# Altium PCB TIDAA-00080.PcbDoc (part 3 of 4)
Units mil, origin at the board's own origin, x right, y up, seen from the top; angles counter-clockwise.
Board outline 7874.02 x 2559.06 mil, 4 copper layers (Top Layer, MidLayer1, MidLayer2, Bottom Layer), stack 61.2 mil thick; 363 components, 169 nets, 940 pads, 199 vias.
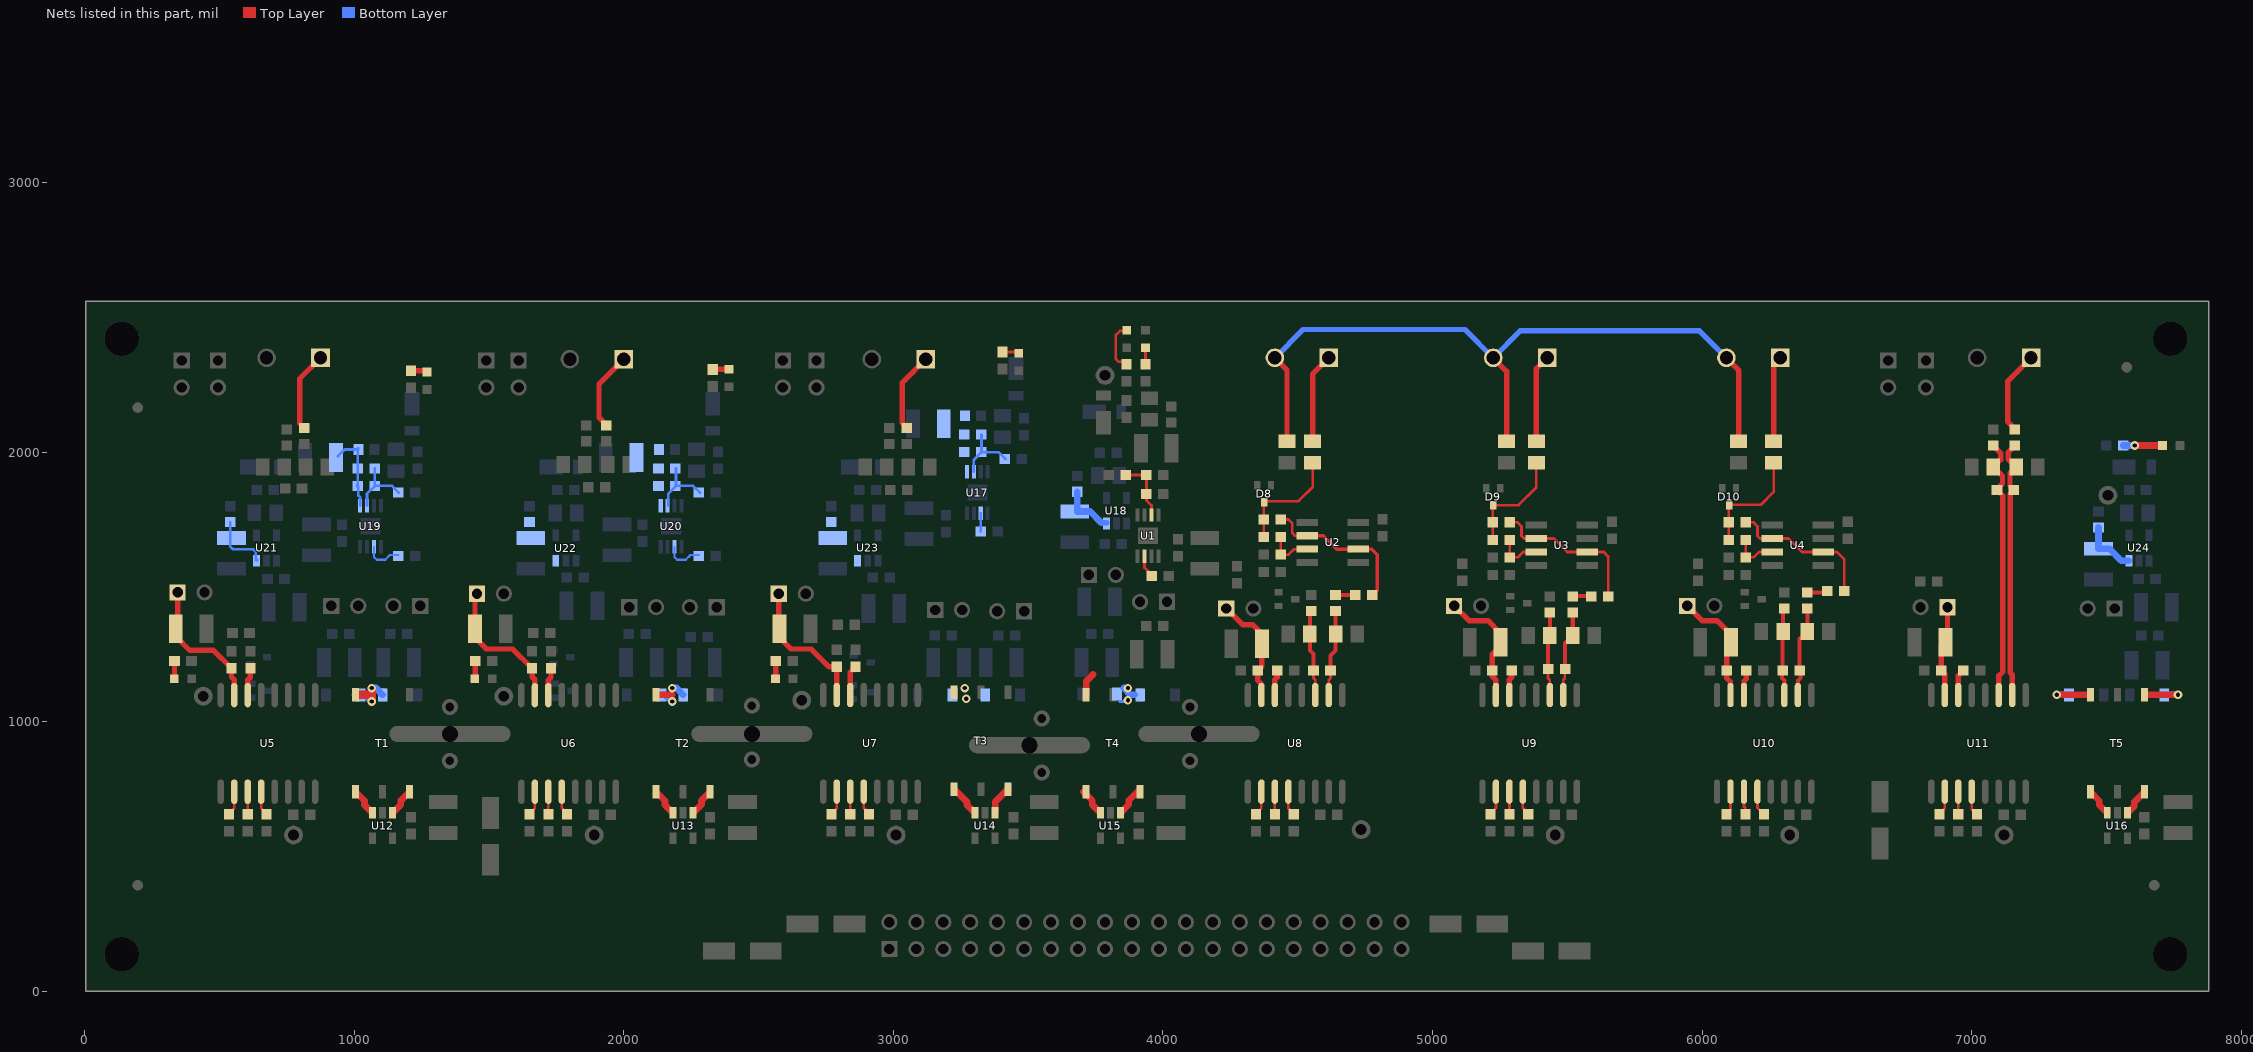
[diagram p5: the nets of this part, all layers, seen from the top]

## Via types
v1: diameter 32, hole 16, Top Layer to Bottom Layer, tented both sides, 199 vias

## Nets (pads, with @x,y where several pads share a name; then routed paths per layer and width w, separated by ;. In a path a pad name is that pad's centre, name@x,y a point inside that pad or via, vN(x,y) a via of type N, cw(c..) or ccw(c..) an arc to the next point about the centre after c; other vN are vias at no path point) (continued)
NetC10_2: C10.2 C16.2 FB16.2 U11.3 | length 986.6
  Top Layer w20: FB16.2@7080,2025.47 7080,2023.5 7107.2,1996.3 7107.2,1972.2 C10.2@7080,1945 7114,1911 7114,1884 7093.5,1863.5 C16.2@7093.5,1860 7115,1838.5 7115,1185 7100,1170 U11.3@7100,1099.13
NetC11_1: C11.1 C16.1 FB6.2 U11.2 | length 971
  Top Layer w20: U11.2@7150,1099.13 7150,1175 7143,1182 7143,1846.5 C16.1@7156.5,1860 7142,1874.5 7142,1922 C11.1@7165,1945 7135.2,1974.8 7135.2,1998.7 FB6.2@7160,2023.5
NetC15_1: C15.1 R14.2 R15.1 U1.2 | length 235
  Top Layer w10: R14.2@3860,1915 R14.2@3861.5,1915 R15.1@3938.5,1915 3938.5,1846.5 C15.1@3940,1845 ; C15.1@3938.5,1845 3938.5,1821.5 3957.4,1802.6 U1.2@3957.4,1767
NetC17_2: C17.2 C46.1 J26.1 U5.7 | length 525.9
  Top Layer w20: C17.2@332.91,1345 345,1357.09 J26.1@345,1480 ; C17.2@342.91,1345 342.91,1312.09 390,1265 477.65,1265 544.15,1198.5 C46.1@545,1198.5 545,1166 555,1156 U5.7@555,1098.82
NetC18_2: C18.2 C47.1 J27.1 U6.7 | length 528.8
  Top Layer w20: J27.1@1455,1475 1447.91,1467.91 C18.2@1447.91,1345 1447.91,1312.09 1490,1270 1587.65,1270 1659.15,1198.5 C47.1@1660,1198.5 1660,1166 1670,1156 U6.7@1670,1098.82
NetC19_2: C19.2 C56.1 J31.1 U11.7 | length 341.2
  Top Layer w20: U11.7@6900,1099.13 6900,1176.5 C56.1@6886.5,1190 6886.5,1279.41 C19.2@6902.09,1295 6910,1302.91 J31.1@6910,1425
NetC21_1: C21.1 R16.2 U2.3 | length 171.8
  Top Layer w10: R16.2@4436.5,1685 C21.1@4436.5,1620 4466.02,1620 4486.02,1640 U2.3@4535,1640
NetC23_1: C23.1 R17.2 U3.3 | length 171.8
  Top Layer w10: R17.2@5286.5,1675 C23.1@5286.5,1610 5316.02,1610 5336.02,1630 U3.3@5385,1630
NetC25_1: C25.1 R18.2 U4.3 | length 171.8
  Top Layer w10: R18.2@6161.5,1675 C25.1@6161.5,1610 6191.02,1610 6211.02,1630 U4.3@6260,1630
NetC27_2: C27.2 U1.6 | length 85.7
  Top Layer w10: U1.6@3931.8,1613.4 3931.8,1571 3932.84,1571 3951,1552.84 3951,1549 C27.2@3960,1540
NetC37_2: C37.2 C51.2 FB19.2 U8.3 | length 315.8
  Top Layer w10: C51.2@4558.5,1190 4558.5,1161.5 4565,1155 U8.3@4565,1105
  Top Layer w15: FB19.2@4550,1410.47 4545,1405.47 C37.2@4545,1325 4545,1265 4558.5,1251.5 C51.2@4558.5,1190
NetC38_2: C38.2 C51.1 FB18.2 U8.2 | length 320.4
  Top Layer w10: U8.2@4615,1100 4615,1155 4621.5,1161.5 C51.1@4621.5,1190 ; C51.1@4619.1,1189.1 C51.1@4620.6,1189.1
  Top Layer w15: C51.1@4621.5,1190 4621.5,1246.5 4640,1265 C38.2@4640,1325 FB18.2@4640,1408.5
NetC40_2: C40.2 C53.2 FB21.2 U9.3 | length 299.6
  Top Layer w10: C53.2@5428.5,1190 5428.5,1161.5 5435,1155 U9.3@5435,1105
  Top Layer w15: C53.2@5428.5,1195 5428.5,1313.5 C40.2@5435,1320 FB21.2@5435,1403.5 ; FB21.2@5435.98,1404.49 FB21.2@5436.5,1405
NetC41_2: C41.2 C53.1 FB20.2 U9.2 | length 326
  Top Layer w10: U9.2@5485,1090 U9.2@5485,1099.13 5485,1155 5490,1160 5490,1190 C53.1@5491.5,1190
  Top Layer w15: C53.1@5491.5,1195 5491.5,1291.5 C41.2@5520,1320 5520,1403.5 FB20.2@5518.5,1405
NetC43_2: C43.2 C55.2 FB23.2 U10.3 | length 328.8
  Top Layer w15: U10.3@6305,1099.13 6305,1153.73 6296,1162.73 6296,1187.5 C55.2@6298.5,1190 6298.5,1333.5 C43.2@6300,1335 6300,1415.47 FB23.2@6305,1420.47
NetC44_2: C44.2 C55.1 FB22.2 U10.2 | length 335.9
  Top Layer w15: U10.2@6355,1099.13 6355,1153.73 6364,1162.73 6364,1187.5 C55.1@6361.5,1190 6361.5,1306.5 C44.2@6390,1335 FB22.2@6390,1418.5
NetC48_1: C48.1 C146.2 J22.1 U7.7 | length 525.6
  Top Layer w20: J22.1@2575,1475 2575,1347.91 C146.2@2577.91,1345 2577.91,1312.09 2620,1270 2695,1270 2761.5,1203.5 C48.1@2790,1203.5 U7.7@2790,1099.13
NetC50_1: C50.1 C147.2 J28.1 U8.7 | length 409.3
  Top Layer w10: U8.7@4365,1099.13 U8.7@4365,1105
  Top Layer w20: J28.1@4235,1420 4295,1360 4332,1360 4367.09,1324.91 C147.2@4367.09,1290 4367.09,1205.59 C50.1@4351.5,1190 4351.5,1153.5 4365,1140 U8.7@4365,1105
NetC52_1: C52.1 C148.2 J29.1 U9.7 | length 454.7
  Top Layer w10: C52.1@5220,1190 C52.1@5221.5,1188.5 ; C52.1@5221.5,1175 C52.1@5221.5,1188.5 ; C52.1@5221.5,1190 C52.1@5221.5,1188.5
  Top Layer w20: J29.1@5080,1430 5135,1375 5205,1375 5252.09,1327.91 C148.2@5252.09,1295 ; C52.1@5221.5,1175 5221.5,1168.5 5235,1155 U9.7@5235,1099.13 ; C52.1@5221.5,1190 5221.5,1251.5 C148.2@5255,1285
NetC54_1: C54.1 C149.2 J30.1 U10.7 | length 421.4
  Top Layer w20: J30.1@5945,1430 6000,1375 6055,1375 6107.09,1322.91 C149.2@6107.09,1295 6091.5,1279.41 C54.1@6091.5,1190 6091.5,1161.5 6105,1147.99 U10.7@6105,1120
NetC84_2: C84.2 C94.2 FB8.1 R59.2 U17.1
NetC88_2: C88.2 C97.2 FB9.1 R61.2 U19.1 | length 302.9
  Bottom Layer w10: C88.2@940,1985 965,2010 FB9.1@1013.5,2010 ; C97.2@1010,1875 1015,1870 1015,1840 1022,1833 U19.1@1022,1802 ; C97.2@1013.5,1876.5 R61.2@1013.5,1940 FB9.1@1013.5,2010 ; FB9.1@1015,2015 1013.5,2013.5 FB9.1@1013.5,2010 ; FB9.1@1015.47,2010 FB9.1@1013.5,2010
NetC91_2: C91.2 C99.2 FB10.1 R62.2 U20.1
NetC94_1: C94.1 R59.1 R63.2 U17.2 | length 242.3
  Bottom Layer w10: U17.2@3298.11,1927 3298.11,1971.1 3327.01,2000 3390.51,2000 R63.2@3415.51,1975 ; C94.1@3327.01,2006.5 R59.1@3327.01,2065
NetC97_1: C97.1 R61.1 R64.2 U19.2 | length 242.3
  Bottom Layer w10: U19.2@1047.6,1802 1047.6,1846.1 C97.1@1076.5,1875 1140,1875 R64.2@1165,1850 ; C97.1@1076.5,1881.5 R61.1@1076.5,1940
NetC99_1: C99.1 R62.1 R65.2 U20.2 | length 242.3
  Bottom Layer w10: U20.2@2165,1802 2165,1846.1 2193.9,1875 2257.4,1875 R65.2@2282.4,1850 ; C99.1@2193.9,1881.5 R62.1@2193.9,1940
NetC110_2: C110.2 U17.6 | length 68.6
  Bottom Layer w8: C110.2@3323.5,1705 3324,1705.5 U17.6@3324,1773.4
NetC111_2: C111.2 FB11.1 U18.3 | length 200.8
  Bottom Layer w20: 3772.4,1737.76 U18.3@3792.4,1737.76
  Bottom Layer w25: FB11.1@3682.4,1853.23 3682.4,1779.84 3730.31,1779.84 3772.4,1737.76
NetC113_2: C113.2 FB12.1 U21.3 | length 228.8
  Bottom Layer w10: FB12.1@540,1740.47 540,1682.09 540,1650 550,1640 625,1640 635,1630 635,1600 U21.3@640,1600
NetC116_2: C116.2 U19.6 | length 139.1
  Bottom Layer w8: U19.6@1073.2,1648.4 1073.2,1610.8 1083,1601 1115,1601 1132.3,1618.3 C116.2@1163.5,1618.3
NetC117_2: C117.2 FB13.1 U22.3
NetC120_2: C120.2 U20.6 | length 139.1
  Bottom Layer w8: U20.6@2188.2,1648.4 2188.2,1610.8 2198,1601 2230,1601 2247.3,1618.3 C120.2@2278.5,1618.3
NetC121_2: C121.2 FB14.1 U23.3
NetC123_2: C123.2 FB15.1 U24.3 | length 209.3
  Bottom Layer w25: FB15.1@7470,1720.47 C123.2@7470,1642.09 7510,1642.09 7554.33,1597.76 U24.3@7582.6,1597.76
NetD1_1: D1.1 R1.1 | length 180.4
  Top Layer w10: R1.1@3865,2335 3835,2335 3825,2345 3825,2435 3840,2450 D1.1@3865,2450
NetD2_2: D2.2 R2.1 | length 68.5
  Top Layer w10: R2.1@3935,2326.5 D2.2@3935,2387.52 D2.2@3935,2395
NetD3_1: D3.1 R5.1 | length 61.7
  Top Layer w10: R5.1@3405,2371.5 3460.98,2371.5 D3.1@3465,2367.48
NetD4_1: D4.1 R3.1 | length 61.7
  Top Layer w20: R3.1@1210,2301.5 1265.98,2301.5 D4.1@1270,2297.48
NetD5_1: D5.1 R4.1 | length 60.4
  Top Layer w20: R4.1@2330,2306.5 2330.98,2307.48 D5.1@2390,2307.48
NetD7_2: D7.2 R60.1 | length 146
  Top Layer w25: v1(7605,2025) D7.2@7707.52,2025
  Bottom Layer w25: R60.1@7561.5,2025 v1(7605,2025)
NetD8_3: D8.3 R6.1 R7.2 R16.1 | length 432.1
  Top Layer w10: R6.1@4372.01,1755 4373.5,1753.5 R16.1@4373.5,1680 ; R6.1@4373.5,1755 4373.5,1817.01 4375,1818.5 4503.5,1818.5 4555,1870 R7.2@4555,1960 ; R6.1@4374.25,1754.25 R6.1@4375,1755
NetD9_3: D9.3 R9.1 R10.2 R17.1 | length 418.3
  Top Layer w10: R9.1@5222.01,1740 5223.5,1738.5 R17.1@5223.5,1675 R17.1@5223.5,1665 ; R9.1@5223.5,1740 5223.5,1802.01 D9.3@5225,1803.5 5318.5,1803.5 5385,1870 R10.2@5385,1960 ; R9.1@5224.25,1739.25 R9.1@5225,1740
NetD10_3: D10.3 R12.1 R13.2 R18.1 | length 425.1
  Top Layer w10: R12.1@6097.01,1741.5 R12.1@6098.5,1740 R18.1@6098.5,1675 ; R12.1@6098.5,1741.5 6098.5,1803.5 6100,1805 6218.5,1805 6265,1851.5 R13.2@6265,1960 ; R12.1@6099.25,1740.75 R12.1@6100,1741.5
NetD14_2: D14.2 R28.1 | length 65.4
  Top Layer w20: D14.2@332.52,1160 333.5,1160.98 R28.1@333.5,1225
NetD15_2: D15.2 R30.1 | length 65.4
  Top Layer w20: D15.2@1447.52,1160 1448.5,1160.98 R30.1@1448.5,1225
NetD16_2: D16.2 R32.1 | length 65.4
  Top Layer w20: D16.2@2562.52,1160 2563.5,1160.98 R32.1@2563.5,1225
NetD29_2: D29.2 D30.1 T1.6 | length 211.3
  Top Layer w25: T1.6@1005,1099.84 T1.6@1005.16,1100
  Top Layer w32: T1.6@1005.16,1100 1065,1100 ; v1(1065,1075) 1065,1100 ; v1(1065,1125) 1065,1100
  Bottom Layer w25: D29.2@1025,1100 1040,1100 v1(1065,1075) ; v1(1065,1125) 1080.53,1125 D30.1@1105.53,1100
NetD32_2: D32.2 D33.1 T2.6 | length 161.3
  Top Layer w25: T2.6@2120,1099.84 2179.84,1099.84 2180,1100
  Bottom Layer w25: D32.2@2140,1100 2155,1100 v1(2180,1075) ; v1(2180,1125) 2195.53,1125 D33.1@2220.53,1100
NetD35_2: D35.2 D36.1 T3.6
  other v1: 3270,1085 3265,1125
NetD37_2: D37.2 D38.1 T4.6 | length 169
  Top Layer w25: T4.6@3715,1099.84 3715,1150 3740,1175
  Bottom Layer w12: 3839.47,1075 3865,1075 v1(3870,1080)
  Bottom Layer w25: v1@3855,1125 3880,1100 3895.53,1100
  other v1: 3870,1125
NetD39_2: D39.2 T5.6 | length 170.6
  Top Layer w25: v1(7315.16,1099.84) T5.6@7440,1099.84
  Bottom Layer w25: v1(7315.16,1099.84) 7315,1100 D39.2@7360.53,1100
NetD40_2: D40.2 T5.4 | length 175.3
  Top Layer w25: T5.4@7640,1099.84 v1(7764.84,1099.84)
  Bottom Layer w25: D40.2@7714.47,1100 7764.68,1100 v1(7764.84,1099.84)
NetFB2_1: FB2.1 J9.1 | length 299.4
  Top Layer w20: FB2.1@815,2089.53 798,2106.53 798,2273 J9.1@875,2350
NetFB4_1: FB4.1 J10.1 | length 294.8
  Top Layer w20: FB4.1@1935,2099.53 1935,2101.5 1908,2128.5 1908,2253 J10.1@2000,2345
NetFB6_1: FB6.1 J15.1 | length 310.7
  Top Layer w20: FB6.1@7160,2086.5 7133,2113.5 7133,2263 J15.1@7220,2350
NetFB7_1: FB7.1 J11.1 | length 296.6
  Top Layer w20: FB7.1@3050,2091.5 3033,2108.5 3033,2258 J11.1@3120,2345
NetFB18_1: FB18.1 R21.2 | length 73.7
  Top Layer w15: FB18.1@4640,1469.53 4640.47,1470 R21.2@4713.5,1470
NetFB20_1: FB20.1 R24.2 | length 69.1
  Top Layer w15: FB20.1@5520,1466.5 5587.01,1466.5 R24.2@5588.5,1465
NetFB22_1: FB22.1 R27.2 | length 70.8
  Top Layer w15: FB22.1@6390,1479.53 6458.03,1479.53 R27.2@6460,1481.5
NetJ12_1: J12.1 R7.1 | length 334.9
  Top Layer w20: R7.1@4555,2040 4555,2290 J12.1@4615,2350
NetJ13_1: J13.1 R10.1 | length 326.6
  Top Layer w20: R10.1@5385,2040 5385,2310 J13.1@5425,2350
NetJ14_1: J14.1 R13.1 | length 320.4
  Top Layer w20: R13.1@6265,2040 6265,2325 J14.1@6290,2350
NetR6_2: R6.2 R21.1 U2.2 U2.6 | length 587
  Top Layer w10: R6.2@4440,1750 4465,1750 4480,1735 4480,1700 4490,1690 U2.2@4535,1690
  Top Layer w12: U2.2@4535,1690 4595,1690 4645,1640 U2.6@4724,1640 4775,1640 4795,1620 4795,1488.5 R21.1@4776.5,1470
NetR9_2: R9.2 R24.1 U3.2 U3.6 | length 586.4
  Top Layer w10: R9.2@5286.5,1740 5315,1740 5330,1725 5330,1690 5340,1680 U3.2@5385,1680 5450,1680 5500,1630 U3.6@5574,1630 5635,1630 5651.5,1613.5 R24.1@5651.5,1465
NetR12_2: R12.2 R27.1 U4.2 U4.6 | length 555.5
  Top Layer w10: R12.2@6161.5,1740 6190,1740 6205,1725 6205,1690 6215,1680 U4.2@6260,1680 6320,1680 6370,1630 U4.6@6445,1630 ; U4.6@6450,1630 6500,1630 6526.5,1603.5 R27.1@6526.5,1485
NetR29_2: R29.2 U5.6 | length 103.8
  Top Layer w20: U5.6@605,1098.82 605,1155 615,1165 R29.2@615,1198.5
NetR31_2: R31.2 U6.6 | length 103.8
  Top Layer w20: U6.6@1720,1098.82 1720,1155 1730,1165 R31.2@1730,1198.5
NetR33_2: R33.2 U7.6 | length 112.7
  Top Layer w20: U7.6@2840,1099.13 2840,1183.5 R33.2@2860,1203.5
NetR34_2: R34.2 U8.6 | length 94.4
  Top Layer w20: U8.6@4415,1099.13 4415,1156.73 4423.5,1165.24 R34.2@4423.5,1190
NetR35_2: R35.2 U9.6 | length 94.4
  Top Layer w20: U9.6@5285,1099.13 5285,1156.73 5293.5,1165.24 R35.2@5293.5,1190
NetR36_2: R36.2 U10.6 | length 94.4
  Top Layer w20: U10.6@6155,1099.13 6155,1150 6163.5,1158.5 R36.2@6163.5,1190
NetR37_2: R37.2 U11.6 | length 98.5
  Top Layer w20: U11.6@6950,1099.13 6950,1155 6950,1171.5 R37.2@6968.5,1190
NetR38_1: R38.1 U5.10 | length 95.9
  Top Layer w10: R38.1@530,655 555,680 U5.10@555,740.55
NetR39_1: R39.1 U5.11 | length 87.6
  Top Layer w10: U5.11@605,740.55 605,660 R39.1@610,655
NetR40_1: R40.1 U5.12 | length 88.8
  Top Layer w10: U5.12@655,740.55 655,680 R40.1@675,660
NetR41_1: R41.1 U6.10 | length 98.8
  Top Layer w10: R41.1@1650,650 1650,660 1670,680 U6.10@1670,740.55
NetR42_1: R42.1 U6.11 | length 95.6
  Top Layer w10: R42.1@1720,645 U6.11@1720,740.55
NetR43_1: R43.1 U6.12 | length 93.8
  Top Layer w10: U6.12@1770,740.55 1770,680 1790,660 R43.1@1790,656.5 R43.1@1790,655
NetR44_1: R44.1 U7.10 | length 89.2
  Top Layer w10: R44.1@2770,660 2790,680 U7.10@2790,740.87
NetR45_1: R45.1 U7.12 | length 94.2
  Top Layer w10: U7.12@2890,740.87 2890,680 2910,660 R45.1@2910,656.5 R45.1@2910,655
NetR46_1: R46.1 U7.11 | length 85.9
  Top Layer w10: R46.1@2840,655 R46.1@2840,656.5 U7.11@2840,740.87
NetR47_1: R47.1 U8.10 | length 94.2
  Top Layer w10: R47.1@4345,655 R47.1@4345,656.5 4345,660 4365,680 U8.10@4365,740.87
NetR48_1: R48.1 U8.11 | length 85.9
  Top Layer w10: R48.1@4415,655 R48.1@4415,656.5 U8.11@4415,740.87
NetR49_1: R49.1 U8.12 | length 94.2
  Top Layer w10: U8.12@4465,740.87 4465,680 4485,660 R49.1@4485,656.5 R49.1@4485,655
NetR50_1: R50.1 U9.10 | length 94.2
  Top Layer w10: R50.1@5215,655 R50.1@5215,656.5 5215,660 5235,680 U9.10@5235,740.87
NetR51_1: R51.1 U9.11 | length 85.9
  Top Layer w10: R51.1@5285,655 R51.1@5285,656.5 U9.11@5285,740.87
NetR52_1: R52.1 U9.12 | length 94.2
  Top Layer w10: U9.12@5335,740.87 5335,680 5355,660 R52.1@5355,656.5 R52.1@5355,655
NetR53_1: R53.1 U10.10 | length 92.1
  Top Layer w10: R53.1@6090,655 R53.1@6090,656.5 6090,660 6105,675 U10.10@6105,740.87
NetR54_1: R54.1 U10.12 | length 96.2
  Top Layer w10: U10.12@6205,740.87 6205,680 R54.1@6230,655
NetR55_1: R55.1 U10.11 | length 82.9
  Top Layer w10: U10.11@6155,740.87 6155,685 6160,680 R55.1@6160,660
NetR56_1: R56.1 U11.10 | length 94.2
  Top Layer w10: R56.1@6880,655 R56.1@6880,656.5 6880,660 6900,680 U11.10@6900,740.87
NetR57_1: R57.1 U11.12 | length 94.2
  Top Layer w10: U11.12@7000,740.87 7000,675 R57.1@7020,655
NetR58_1: R58.1 U11.11 | length 85.9
  Top Layer w10: R58.1@6950,655 R58.1@6950,656.5 U11.11@6950,740.87
NetT1_1: T1.1 U12.3 | length 103.7
  Top Layer w25: T1.1@1005,740 1038,707 1038,691.84 U12.3@1067.6,662.24
NetT1_3: T1.3 U12.1 | length 103.7
  Top Layer w25: U12.1@1142.4,662.24 1173,692.84 1173,708 T1.3@1205,740
NetT2_1: T2.1 U13.3 | length 103.7
  Top Layer w25: T2.1@2120,740 2153,707 2153,691.84 U13.3@2182.6,662.24
NetT2_3: T2.3 U13.1 | length 103.7
  Top Layer w25: U13.1@2257.4,662.24 2288,692.84 2288,708 T2.3@2320,740
NetT3_1: T3.1 U14.3 | length 119.9
  Top Layer w25: T3.1@3225,750 3273,702 3273,691.84 U14.3@3302.6,662.24
NetT3_3: T3.3 U14.1 | length 107.5
  Top Layer w25: U14.1@3377.4,662.24 3377.4,702.4 T3.3@3425,750
NetT4_1: T4.1 U15.3 | length 103.7
  Top Layer w25: T4.1@3705,740 3738,707 3738,691.84 U15.3@3767.6,662.24
NetT4_3: T4.3 U15.1 | length 103.7
  Top Layer w25: U15.1@3842.4,662.24 3873,692.84 3873,708 T4.3@3905,740
NetT5_1: T5.1 U16.3 | length 103.7
  Top Layer w25: T5.1@7440,740 7473,707 7473,691.84 U16.3@7502.6,662.24
NetT5_3: T5.3 U16.1 | length 103.7
  Top Layer w25: U16.1@7577.4,662.24 7603,687.84 7603,703 T5.3@7640,740
NEUTRAL: J12.2 J13.2 J14.2 R8.1 R11.1 R19.1 | length 2832.8
  Top Layer w20: J12.2@4415,2350 4460,2305 R8.1@4460,2040 ; J13.2@5225,2350 5275,2300 R11.1@5275,2040 ; J14.2@6090,2350 6135,2305 R19.1@6135,2040
  Bottom Layer w20: J12.2@4415,2350 4520,2455 5120,2455 J13.2@5225,2350 5325,2450 5990,2450 J14.2@6090,2350
pads on no net: FID1.1 FID2.1 FID3.1 FID4.1 FID5.1 FID6.1 FID7.1 FID8.1 LBL1.0 Logo1.0 MH1.1 MH2.1 MH3.1 MH4.1 T1.5 T2.5 T3.5 T4.5 U1.7 U2.1 U2.5 U2.8 U3.1 U3.5 U3.8 U4.1 U4.5 U4.8 U5.1 U5.4 U5.5 U5.15 U6.1 U6.4 U6.5 U6.15 U7.1 U7.4 U7.5 U7.15 U8.1 U8.4 U8.5 U8.15 U9.1 U9.4 U9.5 U9.15 U10.1 U10.4 U10.5 U10.15 U11.1 U11.4 U11.5 U11.15 U17.7 U18.4 U18.5 U19.7 U20.7 U21.4 U21.5 U22.4 U22.5 U23.4 U23.5 U24.4 U24.5

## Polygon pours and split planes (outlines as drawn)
+3.3V_DVDD on MidLayer1 "MidLayer1-No Net" (solid, pour order 72): 45,785 7830,785 7830,45 45,45
GND_PH on MidLayer1 "Bottom Layer-No Net 1" (solid, remove dead copper, pour order 95): 3680,1065 4140,1065 4145,1070 4150,1065 4750,1065 6495,1065 6560,1130 6560,1195 6565,1200 6565,1840 6565,1935 6430,2070 6425,2075 6155,2075 4175,2075 4090,2160 4090,2215 4090,2440 4045,2485 4040,2490 3835,2490 3770,2490 3705,2425 3650,2370 3650,1590 3650,1095 3680,1065
GND_VSH on MidLayer1 "Bottom Layer-No Net 1" (solid, remove dead copper, pour order 53): 1495,1055 1500,1060 2375,1060 2375,1065 2415,1105 2415,2455 2360,2510 2145,2510 2115,2480 2115,2160 2075,2120 1660,2115 1655,2420 1435,2420 1435,1120 1495,1060
GND_VDC on MidLayer1 "Bottom Layer-No Net 1" (solid, remove dead copper, pour order 92): 7420,1070 7790,1070 7820,1100 7820,2140 7680,2280 7395,2280 7335,2135 7165,2130 6935,2130 6900,2170 6895,2430 6780,2430 6780,2180 6915,2025 7365,2025 7365,1125
GND_XSH1 on MidLayer1 "Bottom Layer-No Net 1" (solid, remove dead copper, pour order 93): 6825,1070 6830,1075 7205,1075 7280,1150 7280,1895 7210,1965 6920,1965 6740,2190 6745,2415 6605,2415 6605,2200 6755,1870 6755,1130 6810,1075 6825,1075
GND_USH on MidLayer1 "Bottom Layer-No Net 1" (solid, remove dead copper, pour order 50): 1265,1035 1265,1040 1305,1080 1305,2430 1250,2485 1035,2485 1005,2455 1005,2135 965,2095 555,2110 555,2420 300,2420 300,1115 380,1035
GND_WSH on MidLayer1 "Bottom Layer-No Net 1" (solid, remove dead copper, pour order 54): 2615,1050 2620,1055 3495,1055 3495,1060 3535,1100 3535,2450 3480,2505 3265,2505 3235,2475 3235,2155 3195,2115 2780,2120 2780,2415 2555,2415 2555,1115 2615,1055
DGND on MidLayer2 "Bottom Layer-No Net" (solid, pour order 76): 45,785 7830,785 7830,45 45,45
+5.0V_VDC on MidLayer2 "Bottom Layer-No Net 1" (solid, remove dead copper, pour order 94): 6835,1055 7285,1055 7475,1055 7755,1055 7775,1075 7790,1090 7790,1195 7790,1920 7740,1970 7735,1975 7415,1975 6805,1975 6760,1930 6755,1925 6755,1120 6755,1110 6810,1055 6835,1055
GND_USH1 on MidLayer2 "Bottom Layer-No Net 1" (solid, remove dead copper, pour order 83): 325,1040 1255,1040 1310,1095 1310,2060 1255,2115 735,2114.98 735,2430 290,2430 290,1075
GND_VSH1 on MidLayer2 "Bottom Layer-No Net 1" (solid, remove dead copper, pour order 82): 1445,1050 2355,1050 2415,1110 2415,2085 2360,2140 1860,2140 1860,2475 1395,2475 1395,1100
GND_WSH1 on MidLayer2 "Bottom Layer-No Net 1" (solid, remove dead copper, pour order 81): 2559.37,1045 3480,1045 3535,1100 3535,2074.37 3480,2129.37 2995,2130 2995,2470 2515,2470 2515,1089.37
-5.0V_PH on MidLayer2 "Bottom Layer-No Net 1" (solid, remove dead copper, pour order 97): 3690,1060 3690,2490 4180,2490 4180,2165 4280,2065 6505,2065 6620,1950 6620,1160 6510,1050 3700,1050
+6V_VSH on Bottom Layer "Bottom Layer-No Net 1" (solid, remove dead copper, pour order 55): 1970,1065 2025,1065 2035,1075 2035,1375 2055,1395 2055,1460 1970,1460 1955,1440 1955,1355 1945,1345 1850,1345 1810,1385 1810,1555 1795,1570 1795,1615 1775,1615 1775,1575 1720,1520 1720,1375 1820,1275 1900,1275 1955,1235 1955,1085
+6V_PH on Bottom Layer "Bottom Layer-No Net 1" (solid, remove dead copper, pour order 67): 3686.52,1100 3718.48,1102.29 3741.3,1125.14 3741.3,1305.71 3755,1319.43 3755,1552.57 3727.61,1580 3686.52,1580 3650,1543.43 3650,1360.57 3672.83,1314.86 3672.83,1118.29
NetD35_2 on Bottom Layer "Bottom Layer-No Net" (solid, remove dead copper, pour order 51): 3205,1140 3350,1140 3370,1140 3380,1130 3385,1125 3385,1095 3385,1080 3375,1070 3235,1070 3200,1070 3195,1075 3195,1130 3195,1135 3200,1140 3205,1140
+6V_WSH on Bottom Layer "Bottom Layer-No Net 1" (solid, remove dead copper, pour order 52): 3075,1075 3145,1075 3145,1080 3170,1105 3175,1110 3175,1320 3175,1435 3155,1455 3105,1455 3095,1455 3085,1445 3085,1355 3075,1345 2975,1345 2970,1345 2955,1360 2940,1375 2940,1545 2930,1555 2925,1560 2920,1560 2915,1565 2915,1605 2915,1610 2910,1615 2900,1615 2895,1610 2895,1575 2895,1560 2885,1550 2885,1490 2885,1300 2910,1275 2920,1265 2985,1265 3040,1265 3065,1240 3070,1235 3070,1105 3070,1080 3075,1075
GND_WSH on Bottom Layer "Bottom Layer-No Net 1" (solid, remove dead copper, pour order 73): 2720,1595 2810,1595 2825,1595 2830,1590 2830,1540 2830,1475 2820,1465 2735,1465 2730,1465 2720,1475 2720,1595
GND_VSH on Bottom Layer "Bottom Layer-No Net 1" (solid, remove dead copper, pour order 74): 1600,1595 1690,1595 1705,1595 1710,1590 1710,1540 1710,1475 1700,1465 1615,1465 1610,1465 1600,1475 1600,1595
GND_USH on Bottom Layer "Bottom Layer-No Net 1" (solid, remove dead copper, pour order 75): 490,1595 580,1595 595,1595 600,1590 600,1540 600,1475 590,1465 505,1465 500,1465 490,1475 490,1595
GND_USH on Bottom Layer "Bottom Layer-No Net 1" (solid, remove dead copper, pour order 70): 760,1365 761.72,1363.28 831.2,1363.28 831.2,1486.72 830,1487.92 830,1505 830,1510 770,1570 765,1575 765,1605 765,1660 800,1695 810,1705 965,1705 1015,1705 1025,1695 1030,1690 1095,1690 1135,1690 1170,1725 1250,1725 1265,1725 1295,1755 1305,1765 1305,1895 1305,1935 1275,1965 1165,1965 1125,1965 1120,1960 1115,1955 1115,1920 1115,1911 1130,1896 1195,1896 1199,1896 1205,1890 1210,1885 1210,1840 1210,1830 1190,1810 1185,1805 1130,1805 1110,1825 1070,1825 1065,1820 1065,1775 1065,1770 1060,1765 975,1765 910,1765 875,1800 870,1805 870,2015 870,2025 850,2045 745,2045 715,2045 695,2025 680,2010 680,1830 680,1745 695,1730 700,1725 720,1725 725,1725 735,1715 736.03,1713.97 736.03,1635.16 735.16,1635.16 730,1630 710,1630 705,1630 703.29,1628.29 703.29,1620 703.29,1581.71 705,1580 725,1560 725,1520 725,1400 760,1365
+6V_USH on Bottom Layer "Bottom Layer-No Net 1" (solid, remove dead copper, pour order 68): 850,1075 910,1075 915,1075 925,1085 935,1095 935,1230 935,1475 880,1475 875,1475 865,1465 855,1455 855,1385 855,1350 850,1345 815,1345 750,1345 720,1375 705,1390 705,1505 705,1540 685,1560 685,1610 685,1615 680,1620 661.65,1620 661.65,1581.65 660,1580 660,1560 660,1555 630,1525 615,1510 615,1375 615,1365 660,1320 700,1280 750,1280 775,1280 830,1225 840,1215 840,1105 840,1085 850,1075
-6V_WSH on Bottom Layer "Bottom Layer-No Net 1" (solid, remove dead copper, pour order 89): 3035,1715 3033.28,1713.28 3033.28,1655.52 3045,1643.8 3243.8,1643.8 3285,1685 3285,1715 3280,1720 3280,1795 3275,1800 3265,1800 3265,1745 3245,1725 3040,1725 3035,1720
GND_WSH on Bottom Layer "Bottom Layer-No Net 1" (solid, remove dead copper, pour order 88): 3235,1165 3370,1165 3410,1205 3410,1445 3245,1445 3205,1405 3205,1195
-6V_WSH on Bottom Layer "Bottom Layer-No Net 1" (solid, remove dead copper, pour order 87): 3440,1075 3500,1075 3510,1085 3515,1090 3515,1180 3515,1435 3505,1445 3455,1445 3445,1435 3445,1430 3445,1390 3445,1360 3445,1355 3435,1345 3430,1340 3430,1255 3430,1085 3440,1075
GND_PH on Bottom Layer "Bottom Layer-No Net 2" (solid, pour order 86): 3905,1670 3920,1655 4075,1655 4095,1675 4095,1820 3885,2055 3885,2195 3800,2190 3800,2005 3815,1985 3815,1740 3885,1740 3905,1720
-6V_PH on Bottom Layer "Bottom Layer-No Net 1" (solid, remove dead copper, pour order 62): 3990,1077.5 4060,1077.5 4065,1082.5 4065,1087.5 4065,1182.5 4065,1407.5 4065,1477.5 4040,1502.5 3990,1502.5 3980,1492.5 3980,1432.5 3980,1087.5 3990,1077.5
GND_VDC on Bottom Layer "Bottom Layer-No Net 1" (solid, remove dead copper, pour order 64): 7405,1570 7510,1570 7525,1555 7525,1510 7515,1500 7475,1500 7460,1485 7460,1390 7460,1375 7435,1350 7370,1350 7360,1350 7340,1370 7340,1555 7355,1570 7410,1570
+6V_VDC on Bottom Layer "Bottom Layer-No Net 1" (solid, remove dead copper, pour order 60): 7465,1075 7605,1075 7635,1105 7635,1270 7650,1285 7655,1290 7655,1465 7655,1485 7640,1500 7640,1550 7635,1555 7600,1555 7595,1555 7590,1550 7590,1510 7590,1485 7570,1465 7565,1460 7505,1460 7500,1460 7490,1450 7485,1445 7485,1380 7485,1180 7465,1160 7460,1155 7460,1085 7460,1080 7465,1075
+5V_CNTL on Bottom Layer "Bottom Layer-No Net 1" (solid, pour order 78): 45,785 7830,785 7830,45 45,45
GND_VDC on Bottom Layer "Bottom Layer-No Net 1" (solid, remove dead copper, pour order 69): 7685,1485 7660,1510 7660,1560 7645,1575 7645,1640 7650,1645 7675,1645 7690,1660 7690,1720 7680,1730 7645,1730 7630,1745 7630,1970 7625,2085 7365,2085 7365,2285 7445,2285 7510,2195 7660,2190 7820,2190 7820,1180 7780,1145 7715,1145 7685,1165
+5.0V_PH on Bottom Layer "Bottom Layer-No Net 1" (solid, remove dead copper, pour order 96): 3650,2085 3655,2090 3775,2090 3785,2100 3785,2225 3790,2230 4010,2230 4155,2085 4155,1125 4210,1070 6495,1070 6610,1185 6610,1900 6460,2050 4405,2050 3980,2475 3730,2475 3645,2390 3647.4,2387.6 3647.4,2102.76
GND_PH on Bottom Layer "Bottom Layer-No Net 1" (solid, remove dead copper, pour order 71): 3805,1165 3905,1165 3945,1205 3945,1460 3880,1510 3880,1575 3795,1575 3795,1180
NetC123_2 on Bottom Layer "Bottom Layer-No Net 4" (solid, pour order 66): 7595,1610 7595,1575 7560,1575 7520,1615 7415,1615 7415,1720 7435,1740 7500,1740 7525,1715 7525,1680
+5.0V_VDC on Bottom Layer "Bottom Layer-No Net 4" (solid, pour order 57): 7520,2050 7520,1995 7590,1995 7610,1975 7610,1755 7595,1740 7530,1740 7510,1760 7450,1760 7450,2035 7465,2050
GND_PH on Bottom Layer "Bottom Layer-No Net 1" (solid, remove dead copper, pour order 77): 3620,1690 3730,1690 3745,1675 3745,1620 3725,1600 3620,1600
GND_WSH on Bottom Layer "Bottom Layer-No Net 1" (solid, remove dead copper, pour order 98): 2995,1360 2970,1380 2970,1555 2950,1575 2935,1575 2930,1580 2930,1625 2970,1625 2964.98,1875 3010,1875 3010,1630 3065,1565 3065,1370 3055,1360
-6V_USH on Bottom Layer "Bottom Layer-No Net 1" (solid, remove dead copper, pour order 65): 1190,1070 1245,1070 1260,1085 1260,1350 1285,1375 1285,1515 1245,1555 1056,1555 1030,1581 1030,1675 1015,1690 925,1690 895,1660 805,1660 790,1645 790,1585 870,1505 1175,1505 1200,1480 1200,1385 1175,1360 1175,1085
GND_USH on Bottom Layer "Bottom Layer-No Net 1" (solid, remove dead copper, pour order 63): 975,1165 1135,1165 1155,1185 1155,1370 1180,1395 1180,1470 1170,1480 995,1480 970,1470 970,1375 960,1350 960,1180
GND_VSH on Bottom Layer "Bottom Layer-No Net 1" (solid, remove dead copper, pour order 61): 1865,1375 1926.2,1375 1930,1380 1930,1509.98 1875,1564.98 1875,1685 1895,1705 2265,1705 2275,1715 2390,1715 2430,1755 2430,1930 2400,1960 2245,1960 2235,1950 2235,1915 2250,1900 2315,1900 2325,1890 2325,1820 2320,1815 2250,1815 2230,1835 2180,1835 2180,1775 2165,1760 2010,1760 1980,1790 1980,2025 1960,2045 1895,2045 1885,2035 1885,2000 1860,1975 1810,1975 1800,1965 1800,1640 1810,1630 1810,1575 1835,1550 1835,1405
GND_VSH on Bottom Layer "Bottom Layer-No Net 1" (solid, remove dead copper, pour order 56): 2090,1165 2250,1165 2275,1185 2275,1445 2255,1465 2105,1465 2090,1450 2090,1380 2060,1345 2060,1195
-6V_VSH on Bottom Layer "Bottom Layer-No Net 1" (solid, remove dead copper, pour order 59): 2320,1070 2385,1070 2400,1085 2400,1490 2345,1545 2215,1545 2210,1580 2165,1585 2145,1615 2145,1670 2130,1685 1925,1685 1900,1660 1900,1575 1965,1485 2270,1485 2290,1470 2290,1465 2295,1460 2295,1095
GND_WSH on Bottom Layer "Bottom Layer-No Net 1" (solid, remove dead copper, pour order 91): 3230,1750 2930,1750 2920,1760 2920,1975 2940,1995 3010,1995 3030,2015 3030,2155 3045,2170 3105,2170 3115,2160 3115,1930 3160,1885 3320,1885 3320,1950 3450,1950 3450,2015 3445,2021 3444,2020 3439,2025 3380,2025 3370,2035 3370,2080 3375,2085 3475,2085 3500,2060 3501,1894 3435,1810 3250,1810 3240,1800 3240,1760
-6V_WSH on Bottom Layer "Bottom Layer-No Net 1" (solid, remove dead copper, pour order 90): 3455,1380 3510,1380 3510,1535 3440,1595 3265,1595 3260,1645 3260,1675 3215,1700 3200,1715 3105,1715 3100,1720 3035,1720 3033.28,1655.52 3180,1510 3405,1510 3445,1470 3445,1390
GND_USH on Top Layer "Bottom Layer-No Net 1" (solid, remove dead copper, pour order 80): 1190,1075 1290,1075 1290,1080 1315,1105 1315,1220 1175,1365 1175,1460 1150,1490 1020,1490 990,1460 990,1345 1175,1160 1175,1090
GND_VSH on Top Layer "Bottom Layer-No Net 1" (solid, remove dead copper, pour order 84): 2270,1075 2370,1075 2370,1080 2395,1105 2395,1210 2395,1220 2295,1320 2280,1335 2280,1420 2280,1455 2260,1475 2255,1480 2125,1480 2115,1480 2100,1465 2095,1460 2095,1415 2095,1320 2245,1170 2255,1160 2255,1095 2255,1090 2270,1075
-6V_PH on Top Layer "Bottom Layer-No Net 1" (solid, remove dead copper, pour order 58): 3990,1410 3980,1420 3980,1500 4085,1500 4105,1515 4105,1565 4102.22,1565 4082.2,1585.02 3975,1585 3975,1630 4185,1630 4210,1605 4210,1485 4125,1410
GND_PH on Top Layer "Top Layer-No Net" (solid, pour order 79): 3985,2145 3975,2155 3750,2155 3750,1780 3770,1755 3770,1215 3960,1215 3960,1475 3930,1505 3900,1505 3885,1520 3885,1650 4210,1650 4210,1730 3965,1730 3965,2066 3985,2086
GND_WSH on Top Layer "Bottom Layer-No Net 1" (solid, remove dead copper, pour order 85): 3410,1070 3510,1070 3510,1075 3535,1100 3535,1215 3420,1330 3420,1450 3395,1475 3255,1475 3235,1455 3225,1440 3225,1325 3395,1155 3395,1085

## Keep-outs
Keep-Out Layer:
  circle w8: c7736.22,137.8 r118.11
  circle w8: c137.8,137.8 r118.11
  circle w8: c137.8,2421.26 r118.11
  circle w8: c7736.22,2421.26 r118.11
  lines w10: -5,0 -5,3450 ; 0,-5 4950,-5

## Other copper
Top Layer:
  region net -6V_PH: 3980,1500 3980,1215 3985,1190 4050,1190 4050,1491.2 4041.2,1500
  region net NetD37_2: 3848.8,1058.28 3860,1050 3875,1050 3888.8,1058.28 3888.8,1168.28 3868.8,1188.28 3728.8,1188.28 3703.8,1163.28 3703.8,1058.28 3753.8,1058.28 3753.8,1134.85 3843.8,1134.85 3848.8,1113.28
  region net NetC9_2: 3975,1740 3975,2060 4000,2085 4000,2120 4010,2130 4050,2130 4060,2120 4060,1755 4045,1740
  region net -5.0V_PH: 4010,2150 4050,2150 4060,2160 4060,2180 4010,2230 3910,2230 3900,2240 3900,2275 3890,2285 3845,2285 3805,2325 3765,2325 3750,2310 3750,2190 3770,2170 3990,2170
  region net NetD29_2: 1080,1070 1070,1060 995,1060 985,1070 985,1130 995,1140 1070,1140 1080,1130
  region net NetD32_2: 2195,1070 2185,1060 2110,1060 2100,1070 2100,1130 2110,1140 2185,1140 2195,1130
  region net NetD35_2: 3300,1075 3290,1065 3215,1065 3205,1075 3205,1135 3215,1145 3290,1145 3300,1135
  text ".Layer_Name" at 577,-858.49 h60
MidLayer1:
  pour cut-out: 40,235 205,235 240,200 240,75 200,35 70,35 70,45 40,75
  pour cut-out: 7655,225 7655,210 7625,180 7630,175 7630,80 7665,45 7810,45 7810,55 7845,90 7840,95 7840,200 7835,200 7795,240 7780,225
  text ".Layer_Name" at 577,-858.49 h60
MidLayer2:
  text ".Layer_Name" at 577,-858.49 h60
Bottom Layer:
  region net +5.0V_PH: 3657.4,1892.76 3717.4,1892.76 3732.4,1877.76 3787.4,1877.76 3787.4,2112.76 3767.4,2132.76 3677.4,2132.76 3647.4,2102.76 3647.4,1902.76
  region net NetC111_2: 3657.4,1872.76 3620,1845 3620,1740 3652.4,1712.76 3802.4,1712.76 3802.4,1757.76 3702.4,1857.76 3702.4,1872.76
  region net +5.0V_USH: 485,1795 500,1780 560,1780 600,1740 665,1740 665,1975 505,1975 485,1955
  region net -5.0V_USH: 1055,1980 1257.64,1980 1257.64,2100 1140,2100 1140,2045 1130,2035 1055,2035
  region net NetC88_2: 1035,2035 1035,1855 1030,1850 1030,1777 1003,1777 990,1790 930,1790 905,1815 905,2035
  region net NetD29_2: 1125,1130 1125,1070 1115,1060 1015,1060 1005,1070 1005,1130 1015,1140 1115,1140
  region net NetD32_2: 2240,1130 2240,1070 2230,1060 2130,1060 2120,1070 2120,1130 2130,1140 2230,1140
  region net NetD37_2: 3930,1130 3930,1070 3920,1060 3820,1060 3810,1070 3810,1130 3820,1140 3920,1140
  pour cut-out: 703.29,1620 703.29,1661.71 705,1710 685,1730 620,1730 620,1620
  pour cut-out: 2937.49,1620 2937.49,1661.71 2939.2,1710 2919.2,1730 2854.2,1730 2854.2,1620
  region net NetC113_2: 560,1760 610,1710 610,1665 650,1625 650,1575 625,1575 625,1605 610,1620 495,1620 485,1630 485,1745 500,1760
  region net NetC117_2: 1670,1759.5 1720,1709.5 1720,1664.5 1760,1624.5 1760,1574.5 1735,1574.5 1735,1604.5 1720,1619.5 1605,1619.5 1595,1629.5 1595,1744.5 1610,1759.5
  region net NetC121_2: 2790,1760 2840,1710 2840,1665 2880,1625 2880,1575 2855,1575 2855,1605 2840,1620 2725,1620 2715,1630 2715,1745 2730,1760
  region net +5.0V_VSH: 1595,1794.5 1610,1779.5 1670,1779.5 1710,1739.5 1775,1739.5 1775,1974.5 1615,1974.5 1595,1954.5
  region net +5.0V_WSH: 2715,1795 2730,1780 2790,1780 2830,1740 2895,1740 2895,1975 2735,1975 2715,1955
  region net NetC91_2: 2150,2035 2150,1855 2145,1850 2145,1775 2050,1775 2020,1790 2020,2035
  region net NetC84_2: 3285.8,2160 3285.8,1980 3280.8,1975 3280.8,1902 3253.8,1902 3240.8,1915 3180.8,1915 3155.8,1940 3155.8,2160
  region net -5.0V_VSH: 2170,1980 2372.64,1980 2372.64,2100 2255,2100 2255,2045 2245,2035 2170,2035
  region net -5.0V_WSH: 3305.8,2105 3508.44,2105 3508.44,2225 3390.8,2225 3390.8,2170 3380.8,2160 3305.8,2160
  text ".Layer_Name" at 577,-858.49 h60

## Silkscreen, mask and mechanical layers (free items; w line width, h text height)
Top Overlay:
  circle w6: c4929.69,1855 r40.31
  circle w6: c4849.69,1330 r40.31
  circle w6: c5744.69,1325 r40.31
  circle w6: c5749.69,1840 r40.31
  circle w6: c6799.69,1690 r40.31
  circle w6: c6609.69,1360 r40.31
  region: 7163.75,355 7163.75,255 7286.25,255 7286.25,355
  lines w6: 355,1090 355,1130 ; 375,1110 355,1110 ; 1780,1165 1775,1170 ; 1780,1175 1775,1170 ; 1840,1170 1775,1170 ; 2511,1186 2531,1166 ; 2910,1175 2905,1180 ; 2910,1185 2905,1180 ; 2970,1180 2905,1180 ; 3845,2092 3845,2070 3857,2058 3857,2025 ; 3875.9,1610.9 3875.9,1766.5 ; 4010.9,1610.9 4010.9,1766.5 ; 4535,1555 4725,1555 ; 4535,1770 4725,1770 ; 4770,1330 4800,1330 ; 4930,1905 4930,1930 ; 5385,1545 5575,1545 ; 5385,1760 5575,1760 ; 5655,1330 5695,1330 ; 5755,1890 5755,1925 ; 6260,1545 6450,1545 ; 6260,1760 6450,1760 ; 6267,1491 6267,1382 6185,1382 6185,1285 6525,1285 6525,1390 6430,1390 6430,1514 6291,1514 ; 6525,1355 6570,1355 ; 6800,1740 6800,1770 ; 355,1110 330,1085 330,1130 350,1110 355,1110 ; 4419,1275.99 4420,1276.99 4420,1290 4420,1380 4517,1380 4517,1504 4675,1504 4675,1380 4765,1380 4765,1285 4755.99,1275.99 4419,1275.99 ; 4775,1945 4780,1940 5075,1940 5075,2015 5010,2015 5010,2160 4855,2160 4855,2015 4775,2015 4775,1945 ; 5313,1368 5399,1368 5399,1498 5555,1498 5555,1380 5650,1380 5650,1276.97 5649.01,1275.99 5314,1275.99 5314,1367 5313,1368 ; 5585,1925 5585,2005 5590,2010 5670,2010 5675,2015 5675,2170 5835,2170 5835,2025 5840,2020 5915,2020 5915,1925 5585,1925 ; 6630,1770 6650,1770 6985,1770 6985,1865 6905,1865 6905,2025 6745,2025 6720,2025 6720,1870 6630,1870 6630,1770
  lines w10: 2920.01,97.19 4950.01,97.19 ; 2920.01,-2.81 4950.01,-2.81 4950.01,302.19 4947.81,300 3085,300 2922.2,300 2920.01,302.19 2920.01,-2.81
  text "C" at 4915,1835 h35
  text "B" at 5735,1820 h35
  text "A" at 6785,1670 h35
  text "A" at 6595,1340 h35
  text "C" at 4835,1310 h35
  text "B" at 5730,1305 h35
  text "2" at 2970,320 h35
  text "40" at 4870,320 h35
  text "ISE3010 REV E1" at 6335,265 h60
  text "TIDA-00080" at 6405,143 h60
  text "1" at 2880,75 h35
  text "39" at 4970,75 h35
  text ".Layer_Name" at 577,-858.49 h60
Bottom Overlay:
  region: 6543.75,215 6543.75,115 6666.25,115 6666.25,215
  lines w6: 945,1845 945,1850 960,1865 980,1865 ; 950,1890 962.22,1890 985.02,1912.8 ; 990,1650 990,1805 ; 1130,1650 1130,1805 ; 1984,1899 2079,1899 2093.5,1913.5 ; 2105,1650 2105,1805 ; 2245,1650 2245,1805 ; 3073,1832 3073,1882 ; 3098,2024 3221.22,2024 3235.02,2037.8 ; 3210,1985 3230,2005 ; 3240,1775 3240,1930 ; 3380,1775 3380,1930
  text "ISE3010  REV E1" at 7535,135 h60
  text ".Layer_Name" at 577,-858.49 h60
Top Paste:
  text ".Layer_Name" at 577,-858.49 h60
Bottom Paste:
  text ".Layer_Name" at 577,-858.49 h60
Top Solder:
  text ".Layer_Name" at 577,-858.49 h60
  text ".Layer_Name" at 577,-858.49 h60
Bottom Solder:
  text ".Layer_Name" at 577,-858.49 h60
Drill Guide:
  text ".Layer_Name" at 577,-858.49 h60
M1 Board Outline:
  lines w10: 0,0 0,2559.06 7874.02,2559.06 7874.02,0 0,0
  text ".Layer_Name" at 558.06,-860.14 h60
M2 Board Dimensions:
  rectangle: -0.5,-285.5 124.5,-160.5
  rectangle: 124.5,-410.5 499.5,-285.5
  lines w7: -0.5,-285.5 999.5,-285.5 ; 124.5,-410.5 124.5,-160.5 ; 249.5,-410.5 249.5,-160.5 ; 499.5,-410.5 499.5,-160.5 ; 749.5,-410.5 749.5,-160.5 ; -0.5,-410.5 999.5,-410.5 999.5,-160.5 -0.5,-160.5 -0.5,-410.5
  lines w10: -0.5,-475.5 -0.5,-455.5 ; 59.5,-485.5 -0.5,-465.5 ; 59.5,-445.5 -0.5,-465.5 ; 223.58,-465.5 -0.5,-465.5 ; 775.42,-465.5 999.5,-465.5 ; 939.5,-485.5 999.5,-465.5 ; 939.5,-445.5 999.5,-465.5 ; 999.5,-475.5 999.5,-455.5
  text "1000 (mil)" at 233.58,-501.49 h60
M3 3D STEP Top:
  text ".Layer_Name" at 577,-858.49 h60
M4 3D STEP Bottom:
  text ".Layer_Name" at 577,-858.49 h60
M5 Assembly Top:
  circle w6: c2893.82,150 r11.18
  lines w10: -292,-930.17 6308,-930.17 ; -292,-726.83 6310,-726.83 ; -292,-523.5 -292,-1133.5 3713,-1133.5 6310,-1133.5 6310,-523.5 -291.5,-523.5 -291.5,-1133.5 1284,-1133.5 ; 2173,-1133.5 2173,-523.5 ; 3440,-726.83 3440,-523.5 ; 4280,-726.83 4280,-523.5 ; 4902,-1140 4902,-937.17
  text "COMPONENTS MARKED 'DNP' SHOULD NOT BE POPULATED." at 1156.04,-361.71 h60
  text "ASSEMBLY VARIANT:" at 1155.54,-477.21 h60
  text ".VariantName" at 2191.54,-477.21 h60
  text "PCB VIEWED FROM TOP SIDE" at -228.5,-655.67 h60
  text "BOARD #:" at 2248,-655.67 h60
  text "REV:" at 3638,-655.67 h60
  text ".PCB_Rev" at 3929.5,-655.67 h60
  text "SVN REV:" at 4476,-655.67 h60
  text ".VersionControl_RevNumber" at 4982,-655.67 h60
  text "TIDA-00080" at 2700,-660 h60
  text "Top Assembly" at 1146.5,-853.49 h60
  text "PLOT NAME =" at -228.5,-1064.34 h60
  text ".plot_File_Name" at 577,-1064.34 h60
  text "GENERATED    :" at 2250,-1064.34 h60
  text ".Print_Date" at 3119.5,-1064.34 h60
  text ".Print_Time" at 3848.5,-1064.34 h60
  text "TEXAS INSTRUMENTS" at 5113,-1064.34 h60
M6 Assembly Bottom:
  lines w10: -292.5,-727.33 6309.5,-727.33 ; -290.5,-930.67 6309.5,-930.67 ; 1115.5,-1140.5 1115.5,-937.67 ; 1737.5,-727.33 1737.5,-524 ; 2577.5,-727.33 2577.5,-524 ; 3844.5,-1134 3844.5,-524 ; 4733.5,-1134 6309,-1134 6309,-524 -292.5,-524 -292.5,-1134 2304.5,-1134 6309.5,-1134 6309.5,-524
  text "COMPONENTS MARKED 'DNP' SHOULD NOT BE POPULATED." at 6102,-318 h60
  text ".VariantName" at 5058,-434 h60
  text "ASSEMBLY VARIANT:" at 6097,-434 h60
  text ".VersionControl_RevNumber" at 1035.5,-656.17 h60
  text "SVN REV:" at 1541.5,-656.17 h60
  text ".PCB_Rev" at 2088,-656.17 h60
  text "REV:" at 2379.5,-656.17 h60
  text "TIDA-00080" at 3224,-656.17 h60
  text "BOARD #:" at 3769.5,-656.17 h60
  text "PCB VIEWED FROM BOTTOM SIDE" at 6246,-656.17 h60
  text "Bottom Assembly" at 1490,-835 h60
  text "TEXAS INSTRUMENTS" at 904.5,-1064.84 h60
  text ".Print_Time" at 2169,-1064.84 h60
  text ".Print_Date" at 2898,-1064.84 h30
  text "GENERATED    :" at 3767.5,-1064.84 h30
  text ".plot_File_Name" at 5440.5,-1064.84 h60
  text "PLOT NAME =" at 6246,-1064.84 h60
M7 LPKF Text Top:
  lines w10: 3650,420 3650,2570 ; 4070,335 4070,2440 ; 4170,-125 4170,2435 ; 4840,-120 4840,2445 ; 4940,-130 4940,2435 ; 4940,-50 4940,2515 ; 5040,-60 5040,2505 ; 5710,-170 5710,2440 ; 5710,-145 5710,2435 ; 5710,-35 5710,2530 ; 5810,-85 5810,2480 ; 5810,-45 5810,2520 ; 5910,-95 5910,2470 ; 6380,-165 6380,2440 ; 7028,-165 7028,2430
M9 Title Sheet:
  drawing of 57 lines, arcs and shapes, not listed
  text "1" at 739.84,8036.5 h70
  text "2" at 3235.5,8036.5 h70
  text "3" at 5724.84,8036.5 h70
  text "4" at 8231.51,8036.5 h70
  text "5" at 10730.5,8036.5 h70
  text "6" at 13235.5,8036.5 h70
  text "A" at -416.5,6893.5 h70
  text "A" at 14383.5,6893.5 h70
  text "B" at -416.5,4513.5 h70
  text "B" at 14383.5,4513.5 h70
  text "C" at -416.5,2138.5 h70
  text "C" at 14383.5,2138.5 h70
  text "PROJECT TITLE:" at 11343.5,277.5 h45
  text ".PRJ_Title" at 11393.5,144.17 h70
  text "DESIGNED FOR:" at 11343.5,-23.5 h45
  text ".PRJ_Customer" at 11393.5,-163.5 h70
  text "D" at -416.5,-231.5 h70
  text "D" at 14383.5,-231.5 h70
  text "FILE NAME:" at 11343.5,-323.5 h45
  text ".prj_number" at 11393.5,-443.5 h70
  text "Texas Instruments (TI) and/or its licensors do not warrant the accuracy or completeness of this specification" at 6374,-605.34 h45
  text "ENGINEER:" at 11343.5,-613.5 h45
  text "LAYOUT BY:" at 12848.5,-613.5 h45
  text "or any information contained therein. TI and/or its licensors do not warrant that this design will meet" at 6329.01,-718 h45
  text ".prj_engineer" at 11615,-730 h70
  text "the specifications, will be suitable for your application or fit for any particular purpose, or will operate in" at 6329.01,-830.67 h45
  text "ALTIUM DESIGNER VERSION:" at 12848.5,-923.5 h45
  text "an implementation. TI and/or its licensors do not warrant that the design is production worthy. You should" at 6329.01,-943.33 h45
  text "completely validate and test your design implementation to confirm the system functionality for your application." at 6374,-1056 h45
  text ".print_Scale" at 11393.5,-1056.83 h70
  text ".Application_BuildNumber" at 12899,-1056.83 h70
  text "1" at 739.84,-1263.5 h70
  text "2" at 3235.5,-1263.5 h70
  text "3" at 5724.84,-1263.5 h70
  text "4" at 8231.51,-1263.5 h70
  text "5" at 10730.5,-1263.5 h70
  text "6" at 13235.5,-1263.5 h70
M10 Fab Notes:
  drawing of 215 lines, arcs and shapes, not listed
  text "DESIGN INFORMATION" at 12381.02,6810 h60
  text "(REFER ALSO ARRAY/PANEL PROFILING INFORMATION)" at 12019.46,6648.29 h60
  text "BOARD SIZE" at 11333.46,6644 h60
  text "2559MIL" at 11795.78,6516.18 h60
  text "X" at 12301.46,6516.18 h60
  text "7874MIL" at 12532.78,6516.18 h60
  text "Number of Layers :" at 11736.46,6379 h60
  text "4" at 12831.27,6369 h60
  text "MIN. TRACK WIDTH:" at 11736.46,6240 h60
  text "8" at 12832.7,6240 h60
  text "MIL" at 12987.46,6240 h60
  text "MIN. CLEARANCE:" at 11736.46,6108 h60
  text "8" at 12832.7,6108 h60
  text "MIL" at 12987.46,6108 h60
  text "MIN. VIA PAD SIZE:" at 11736.46,5976 h60
  text "24" at 12802.71,5976 h60
  text "MIL" at 12987.46,5976 h60
  text "0.05mm (2MIL)" at 12431.46,5834.29 h60
  text "MINIMUM ANNULAR RING" at 11407.23,5830 h60
  text "EXTERNAL" at 13139.46,5830 h60
  text "PER" at 11607.23,5712 h60
  text "IPC-D-275 CLASS 2 LEVEL C" at 11827.23,5712 h60
  text "MIL, HOLES" at 13315.46,5599.71 h60
  text "+/-" at 12923,5599 h60
  text "+/-" at 13777,5599 h60
  text "REGISTRATION TOLERANCES:" at 11407.23,5594 h60
  text "METAL" at 12607,5594 h60
  text "5" at 13183.2,5594 h60
  text "3" at 14016.2,5594 h60
  text "MIL" at 14132.46,5594 h60
  text "VIA'S TO BE TENTED" at 11465,5505 h60
  text "MATERIAL:" at 11332.46,5324.54 h60
  text "FR-4 High Tg" at 12318.9,5184.21 h60
  text "FR-408" at 11753.46,5175.64 h60
  text "X" at 12165.46,5175.64 h60
  text "OTHER" at 13241.46,5175.64 h60
  text "63MIL (1.6mm) +/-10%" at 12073.56,5012.92 h60
  text "THICKNESS:" at 11407.23,5008.64 h60
  text "X" at 11945.4,5008.64 h60
  text "OTHER" at 13358.46,5008.64 h60
  text "TOLERANCE:" at 11407.23,4850.64 h60
  text "X" at 12246.53,4850.64 h60
  text "ANSI IPC-6012 TYPE 3 CLASS 2" at 12433.48,4850.64 h60
  text "OTHER +/-" at 12433.46,4694.64 h60
  text "BOW & TWIST:" at 11407.23,4537.64 h60
  text "X" at 12246.53,4537.64 h60
  text "ANSI IPC-6012 TYPE 3 CLASS 2" at 12433.48,4537.64 h60
  text "OTHER +/-" at 12433.46,4379.13 h60
  text "COPPER THICKNESS (FINISHED):" at 11332.46,4243.64 h60
  text "1.4MIL (1oz)" at 12212.46,4090.92 h60
  text "2MIL (1.4oz)" at 12979.46,4090.92 h60
  text "2.8MIL (2oz)" at 13706.46,4090.92 h60
  text "OUTER:" at 11689.46,4086.64 h60
  text "X" at 13580,4080 h60
  text "X" at 12855,3940 h60
  text "1.4MIL (1oz)" at 12212.46,3933.92 h60
  text "2.8MIL (2oz)" at 12979.46,3933.92 h60
  text "N/A" at 13706,3934.29 h60
  text "INNER SIGNAL:" at 11400.38,3929.64 h60
  text "DRILLING:" at 11332.46,3790.64 h60
  text "REFERENCE:" at 11407.23,3673.64 h60
  text "X" at 12055.46,3673.64 h60
  text "AS SHOWN" at 12242.46,3673.64 h60
  text "X" at 12956.46,3673.64 h60
  text "NC_DRILL FILES" at 13093.46,3673.64 h60
  text "PTH MIN COPPER THICKNESS:" at 11407.23,3515.64 h60
  text "X" at 12757.46,3515.64 h60
  text "1MIL" at 12894.46,3515.64 h60
  text "OTHER" at 13391.46,3515.64 h60
  text "BOARD FINISH:" at 11332.46,3356.64 h60
  text "SILKSCREEN:" at 11487.68,3238.64 h60
  text "X" at 12436.46,3238.64 h60
  text "TOP" at 12562.46,3238.64 h60
  text "X" at 12946.46,3238.64 h60
  text "BOTTOM" at 13073.46,3238.64 h60
  text "SILKSCREEN COLOR:" at 11487.68,3071.64 h60
  text "X" at 12435.42,3071.64 h60
  text "WHITE" at 12562.46,3071.64 h60
  text "OTHER" at 13073.46,3071.64 h60
  text "SOLDER RESIST COLOR:" at 11487.68,2901.64 h60
  text "X" at 12055.42,2742.44 h60
  text "GREEN" at 12182.46,2742.44 h60
  text "BLUE" at 12773.46,2742.44 h60
  text "OTHER" at 13311.46,2742.44 h60
  text "IMMERSION GOLD (ENIG)" at 12393.46,2553.92 h60
  text "ENEPIG" at 13731,2550.64 h60
  text "SURFACE FINISH:" at 11332.46,2549.64 h60
  text "X" at 12206.51,2549.64 h60
  text "IMM. TIN/SILVER OR EQUIV" at 11662,2392.64 h60
  text "OTHER" at 13093.46,2392.64 h60
  text "ARRAY/PANEL:" at 11332.46,2213.64 h60
  text "CUT AND TRIM PER MECH LAYER 1" at 12393.46,2209.35 h60
  text "N.C. ROUTE" at 12393.46,2057.64 h60
  text "X" at 13072.46,2057.64 h60
  text "V. SCORE" at 13259.46,2057.64 h60
  text "CERTIFICATION:" at 11332.46,1920.64 h60
  text "MATERIALS AND WORKMANSHIP FOR ALL PCBS" at 12057.46,1920.64 h60
  text "TO MEET OR EXCEED THE REQUIREMENTS OF:" at 12057.46,1822.64 h60
  text "X" at 11683.96,1686.13 h60
  text "ANSI IPC-A-600F CLASS ->" at 11822.96,1686.13 h60
  text "X" at 13462.02,1686.13 h60
  text "2" at 13580.96,1686.14 h60
  text "1" at 13265.96,1684.64 h60
  text "3" at 13934.96,1684.64 h60
  text "X" at 11686.02,1526.64 h60
  text "UL 94V-0" at 11822.96,1526.64 h60
  text "X" at 12498.02,1526.64 h60
  text "RoHS" at 12634.96,1526.64 h60
  text "OTHER" at 13279.36,1526.64 h60
  text "PER ORDER" at 13676.42,1526.64 h60
  text "ADDITIONAL REQUIREMENTS:" at 11332.46,1385.64 h60
  text "MICROSECTION:" at 11407.23,1270.64 h60
  text "YES" at 12312.96,1270.64 h60
  text "REQUIRED" at 13174.46,1114.49 h60
  text "BARE BOARD ELEC. TEST:" at 11407.23,1111.64 h60
  text "NONE" at 12712.96,1111.64 h60
  text "X" at 13047.46,1111.64 h60
  text "PER ORDER" at 13766.46,1111.64 h60
  text "MANUFACTURER'S UL:" at 11407.23,954.64 h60
  text "RAIL" at 12572.96,950.35 h60
  text "METAL" at 13064.77,950.35 h60
  text "X" at 13440,950 h60
  text "SILK" at 13576.46,950.35 h60
M11 Gerber Information:
  lines w10: -292,-930.17 6308,-930.17 ; -292,-726.83 6310,-726.83 ; -292,-523.5 -292,-1133.5 3713,-1133.5 6310,-1133.5 6310,-523.5 -291.5,-523.5 -291.5,-1133.5 1284,-1133.5 ; 2173,-1133.5 2173,-523.5 ; 3440,-726.83 3440,-523.5 ; 4280,-726.83 4280,-523.5 ; 4902,-1140 4902,-937.17
  text "ALL ARTWORK VIEWED FROM TOP SIDE" at -228.5,-655.67 h60
  text "BOARD #:" at 2248,-655.67 h60
  text "REV:" at 3638,-655.67 h60
  text ".PCB_Rev" at 3929.5,-655.67 h60
  text "SVN REV:" at 4476,-655.67 h60
  text ".VersionControl_RevNumber" at 4982,-655.67 h60
  text ".PRJ_Number" at 2700,-660 h50
  text "LAYER NAME =" at -228.5,-858.49 h60
  text "PLOT NAME =" at -228.5,-1064.34 h60
  text ".plot_File_Name" at 577,-1064.34 h60
  text "GENERATED    :" at 2250,-1064.34 h60
  text ".Print_Date" at 3119.5,-1064.34 h60
  text ".Print_Time" at 3848.5,-1064.34 h60
  text "TEXAS INSTRUMENTS" at 5113,-1064.34 h60
M12 Stackup:
  lines w6: 11365,7700.5 14240,7700.5 ; 11365,7813.1 14240,7813.1 ; 11305,6976 ccw(c11341,6976) 11341,6940 14264,6940 ccw(c14264,6976) 14300,6976 14300,7914 ccw(c14264,7914) 14264,7950 11341,7950 ccw(c11341,7914) 11305,7914 11305,6976
  text "Layer Stack Up Detail for: ISE_MCS_SDM_E1.PcbDoc" at 11365,7842.95 h52
  text "Layer" at 11365,7771.1 h26
  text "Gerber" at 12371.14,7771.1 h26
  text "Copper" at 13031.52,7771.1 h26
  text "Dielectric" at 13734.35,7771.1 h26
  text "Name" at 11365,7719.1 h26
  text "Document" at 12371.14,7719.1 h26
  text "Thickness" at 13031.52,7719.1 h26
  text "Material" at 13734.35,7719.1 h26
  text "Top Solder Mask" at 11365,7644.9 h36
  text "(.GTS)" at 12371.14,7644.9 h36
  text "Solder Resist" at 13734.35,7644.9 h36
  text "Top Layer" at 11365,7539.69 h36
  text "(.GTL)" at 12371.14,7539.69 h36
  text "2.8mil" at 13031.52,7539.69 h36
  text "FR-4" at 13734.35,7487.08 h36
  text "MidLayer1" at 11365,7434.48 h36
  text "(.G1)" at 12371.14,7434.48 h36
  text "2.8mil" at 13031.52,7434.48 h36
  text "FR-4" at 13734.35,7381.88 h36
  text "MidLayer2" at 11365,7329.27 h36
  text "(.G2)" at 12371.14,7329.27 h36
  text "2.8mil" at 13031.52,7329.27 h36
  text "FR-4" at 13734.35,7276.67 h36
  text "Bottom Layer" at 11365,7224.06 h36
  text "(.GBL)" at 12371.14,7224.06 h36
  text "2.8mil" at 13031.52,7224.06 h36
  text "Bottom Solder Mask" at 11365,7118.85 h36
  text "(.GBS)" at 12371.14,7118.85 h36
  text "Solder Resist" at 13734.35,7118.85 h36
M13 Component Bodies Top:
  text ".Layer_Name" at 577,-858.49 h60
M14 Component Bodies Bottom:
  text ".Layer_Name" at 577,-858.49 h60
M15 Courtyards Top:
  text ".Layer_Name" at 577,-858.49 h60
M16 Courtyards Bottom:
  text ".Layer_Name" at 577,-858.49 h60
Drill Drawing:
  text ".legend" at 101.29,3395.49 h60
  text "Drill Table" at 101.29,3284.8 h60
  text ".Layer_Name" at 577,-858.49 h60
